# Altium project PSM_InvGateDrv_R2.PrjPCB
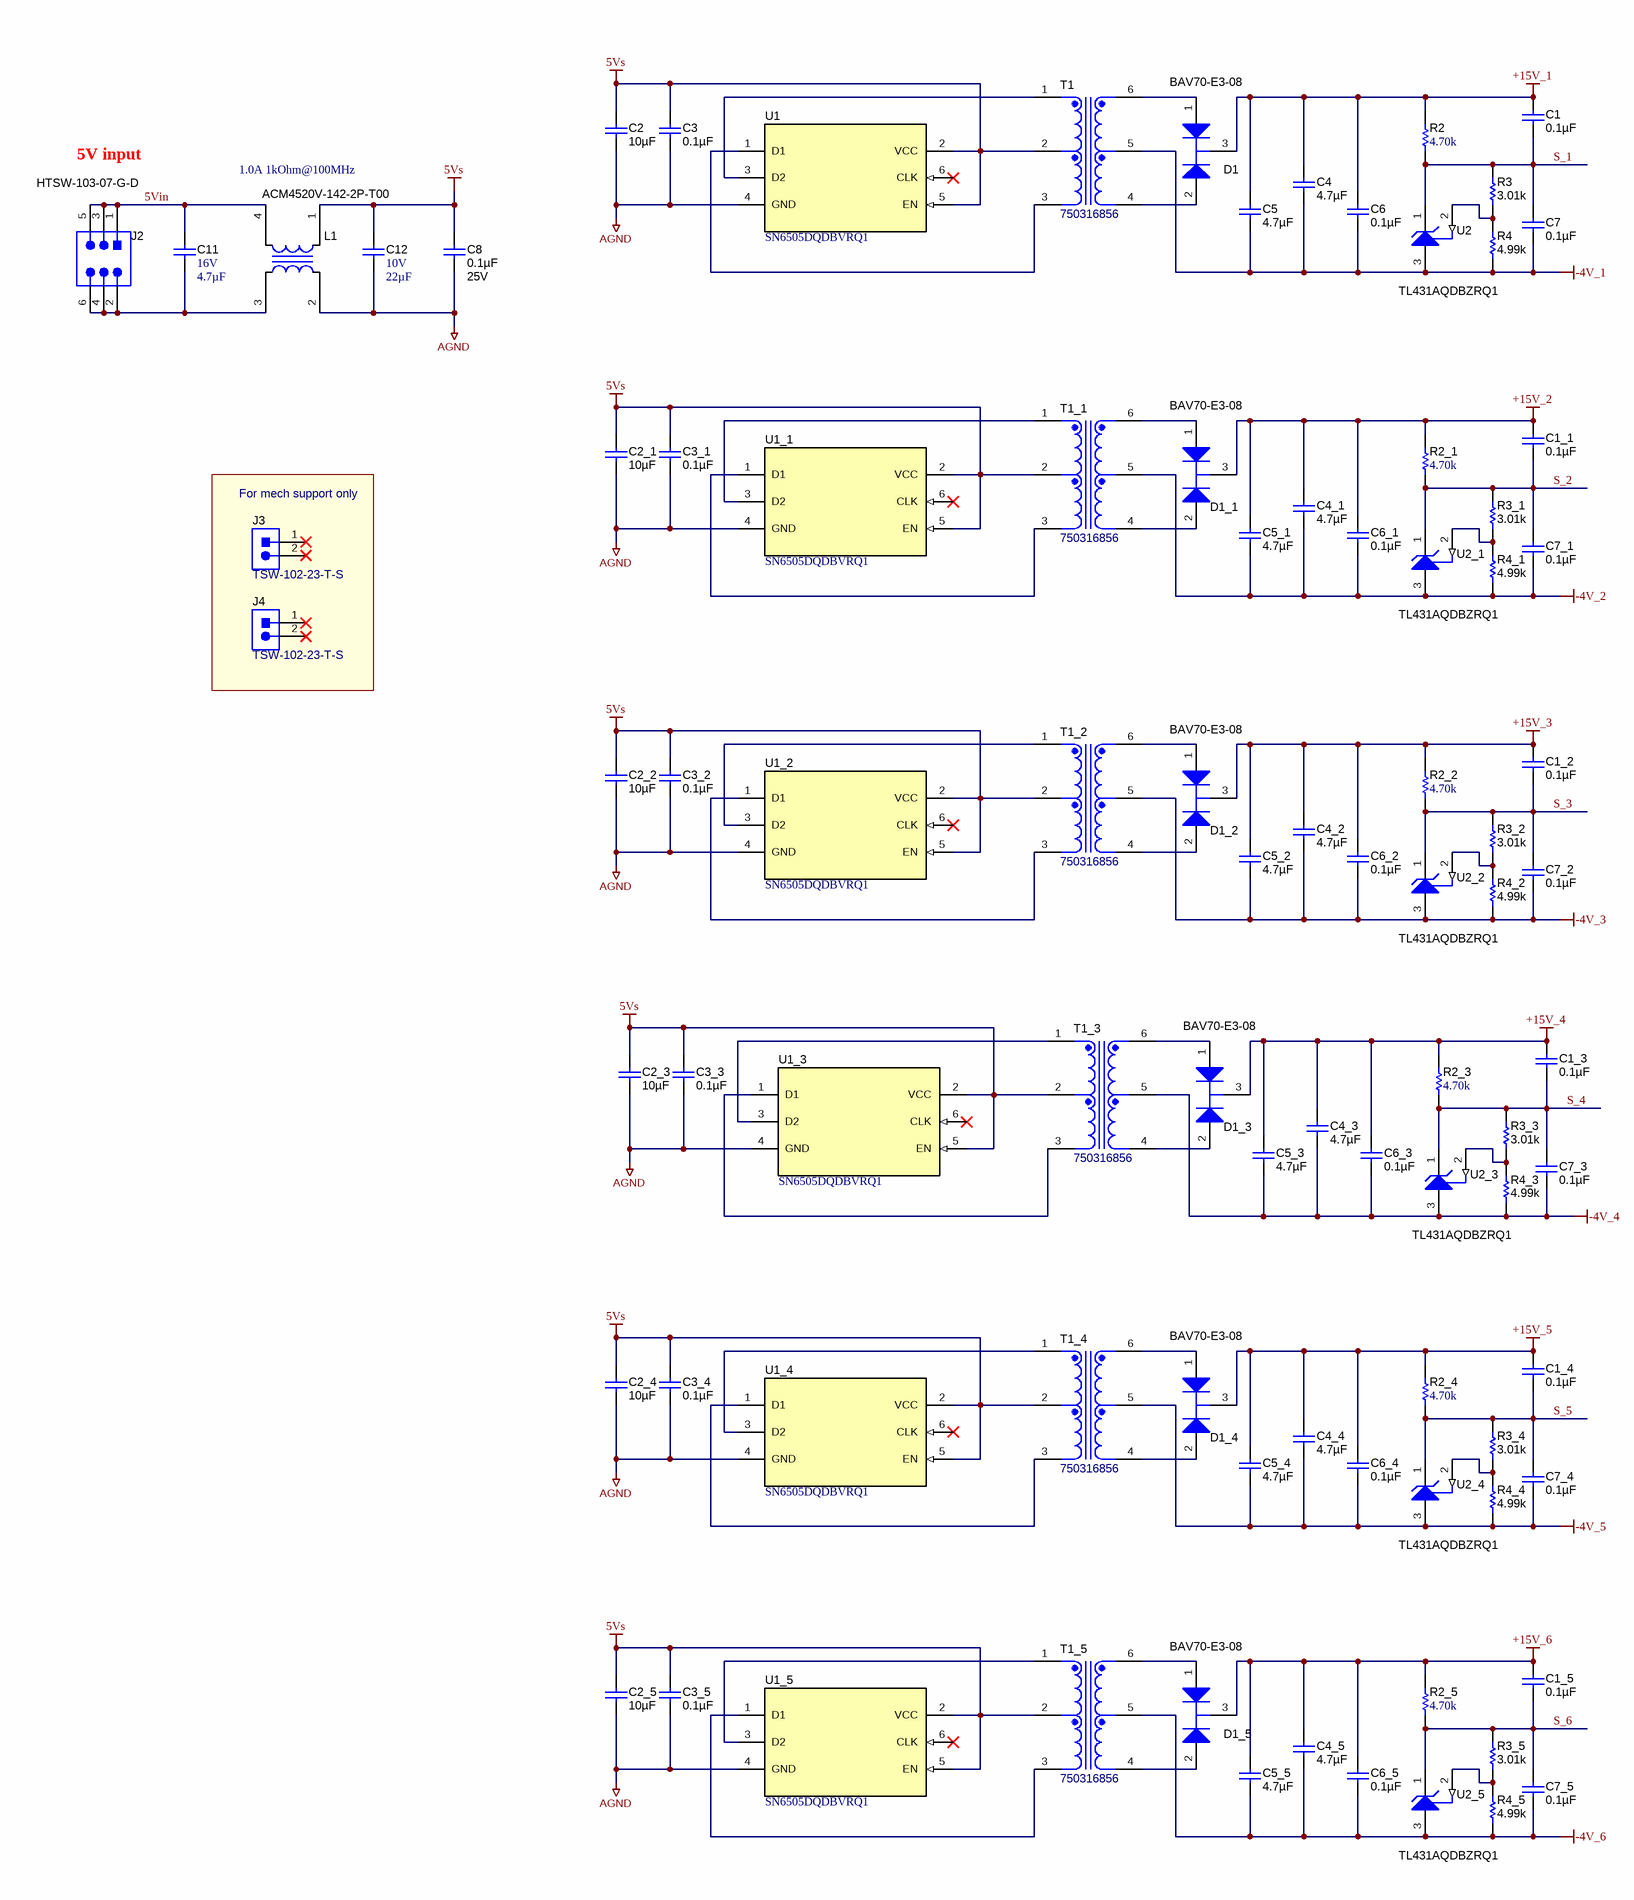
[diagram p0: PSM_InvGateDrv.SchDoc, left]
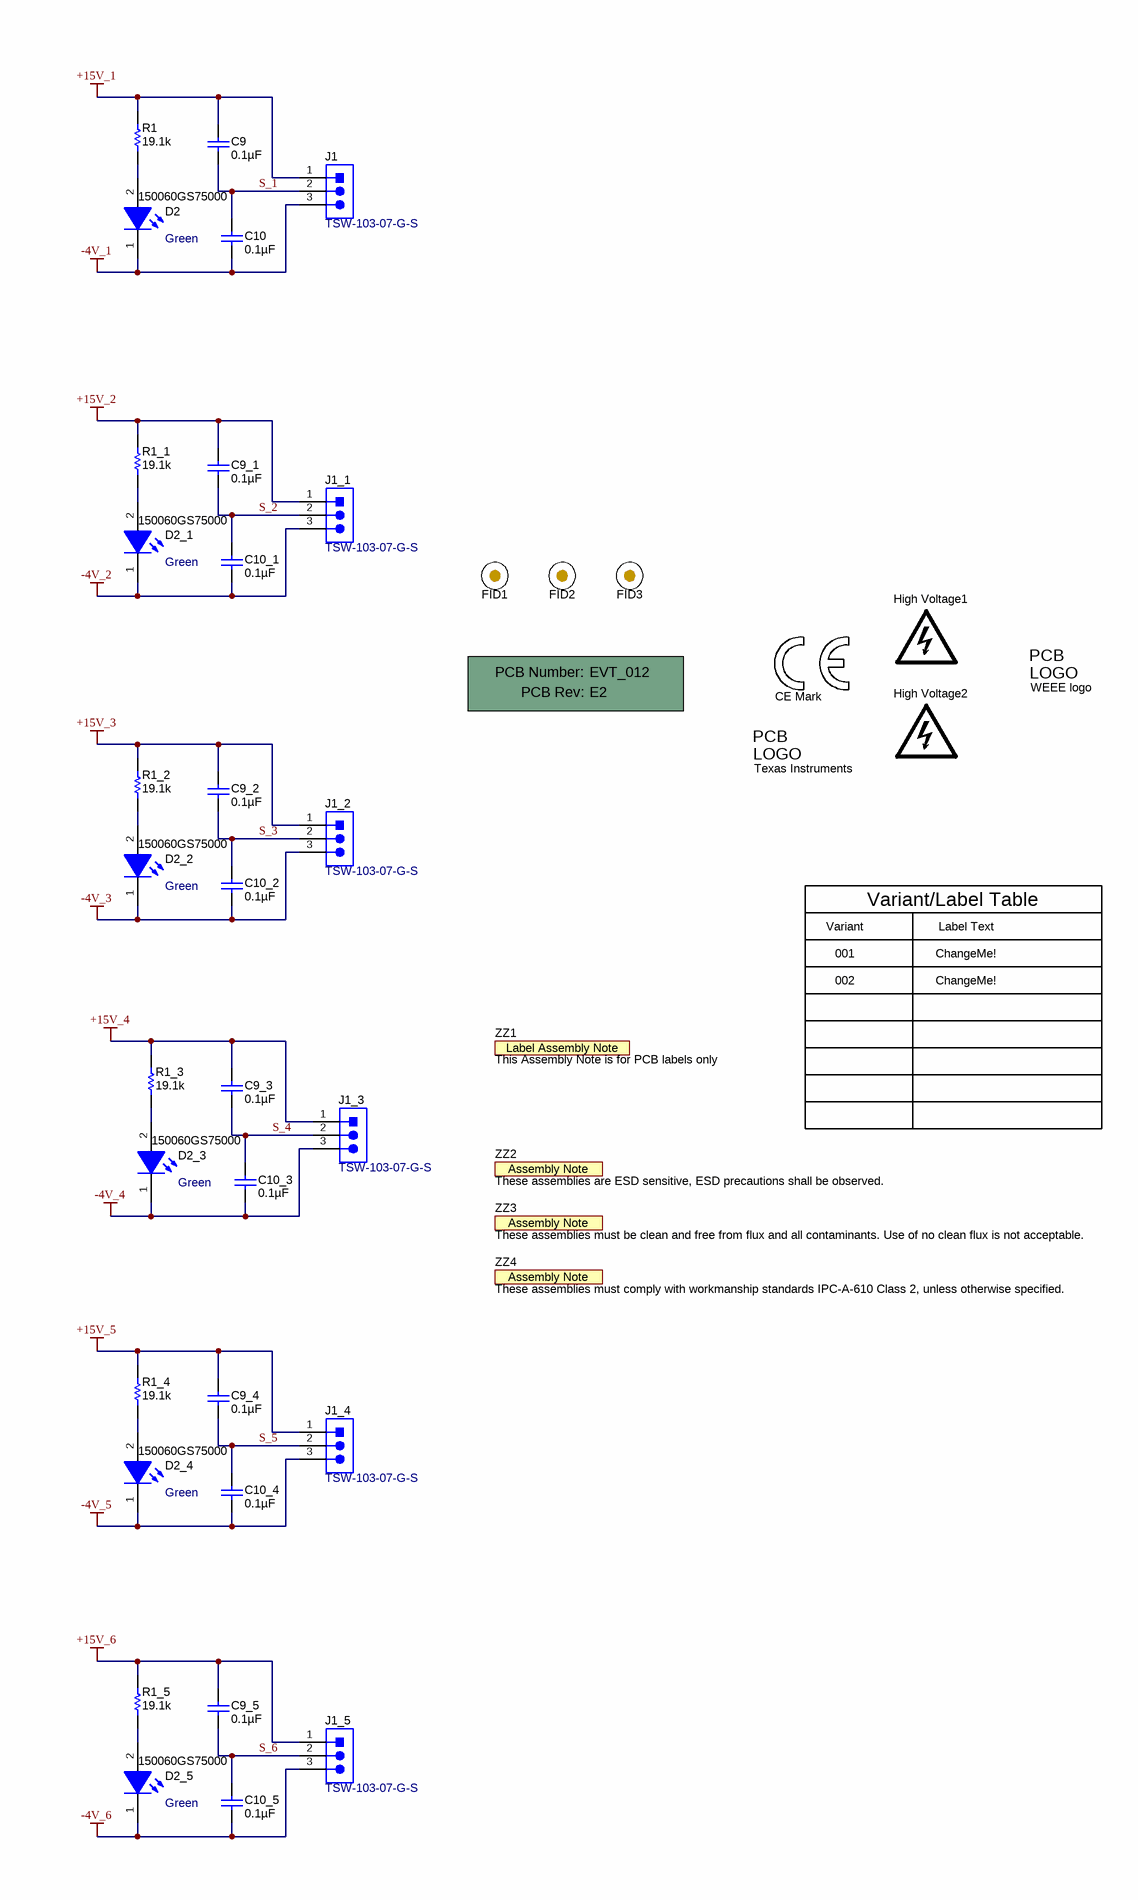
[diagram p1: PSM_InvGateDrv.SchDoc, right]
CopyrightYear: 2019; PCB_Layout: X. Gong / R,Ramesh; PCB_Rev: E2; PRJ_Customer: Public Release; PRJ_Engineer: X.Gong; PRJ_Number: EVT_012; PRJ_Title: Power supply for Traction Gate Driver; SCH_Rev: E2; TechSupport: http://www.ti.com/support; TID: N/A
1 sheet, 134 parts. Net scope: global (net labels, ports and power ports of the same name join across sheets).
Board file: PSM_InvGateDrv_r2.PcbDoc

## Sheet PSM_InvGateDrv.SchDoc
size A2; Date: Not shown in title block; ApprovedBy: Not shown in title block; CheckedBy: Not shown in title block; Author: Not shown in title block; CompanyName: Not shown in title block; Engineer: Not shown in title block; Organization: Not shown in title block; Address1: Not shown in title block; Address2: Not shown in title block; Address3: Not shown in title block; Address4: Not shown in title block; DocumentNumber: 1; Revision: Use project parameter SCH_Rev; SheetNumber: 2; SheetTotal: 3; PageSetup: Record=PageOptions¦CenterHorizontal=True¦CenterVertical=True¦PrintScale=1.00¦XCorrection=1.00¦YCorrection=1.00¦PrintKind=0¦BorderSize=5000000¦LeftOffset=0¦BottomOffset=0¦Orientation=2¦PaperLength=1000¦PaperWidth=1000¦Scale=100¦PaperSource=15¦PrintQuality=600¦MediaType=1¦DitherType=10¦PaperKind=Letter¦PrintScaleMode=1

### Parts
!PCB1  Printed Circuit Board  (value not drawn)  (mechanical)
C1  ValueDisplayed: 0.1µF  [0603]  (hidden comment: CGA3E2X7R1E104K080AA)
C1_1  ValueDisplayed: 0.1µF  [0603]  (hidden comment: CGA3E2X7R1E104K080AA)
C1_2  ValueDisplayed: 0.1µF  [0603]  (hidden comment: CGA3E2X7R1E104K080AA)
C1_3  ValueDisplayed: 0.1µF  [0603]  (hidden comment: CGA3E2X7R1E104K080AA)
C1_4  ValueDisplayed: 0.1µF  [0603]  (hidden comment: CGA3E2X7R1E104K080AA)
C1_5  ValueDisplayed: 0.1µF  [0603]  (hidden comment: CGA3E2X7R1E104K080AA)
C2  ValueDisplayed: 10µF  [0603]  (hidden comment: GRT188C81A106ME13D)
C2_1  ValueDisplayed: 10µF  [0603]  (hidden comment: GRT188C81A106ME13D)
C2_2  ValueDisplayed: 10µF  [0603]  (hidden comment: GRT188C81A106ME13D)
C2_3  ValueDisplayed: 10µF  [0603]  (hidden comment: GRT188C81A106ME13D)
C2_4  ValueDisplayed: 10µF  [0603]  (hidden comment: GRT188C81A106ME13D)
C2_5  ValueDisplayed: 10µF  [0603]  (hidden comment: GRT188C81A106ME13D)
C3  ValueDisplayed: 0.1µF  [0603]  (hidden comment: CGA3E2X7R1E104K080AA)
C3_1  ValueDisplayed: 0.1µF  [0603]  (hidden comment: CGA3E2X7R1E104K080AA)
C3_2  ValueDisplayed: 0.1µF  [0603]  (hidden comment: CGA3E2X7R1E104K080AA)
C3_3  ValueDisplayed: 0.1µF  [0603]  (hidden comment: CGA3E2X7R1E104K080AA)
C3_4  ValueDisplayed: 0.1µF  [0603]  (hidden comment: CGA3E2X7R1E104K080AA)
C3_5  ValueDisplayed: 0.1µF  [0603]  (hidden comment: CGA3E2X7R1E104K080AA)
C4  ValueDisplayed: 4.7µF  [0805_HV]  (hidden comment: GRT21BR61H475KE13L)
C4_1  ValueDisplayed: 4.7µF  [0805_HV]  (hidden comment: GRT21BR61H475KE13L)
C4_2  ValueDisplayed: 4.7µF  [0805_HV]  (hidden comment: GRT21BR61H475KE13L)
C4_3  ValueDisplayed: 4.7µF  [0805_HV]  (hidden comment: GRT21BR61H475KE13L)
C4_4  ValueDisplayed: 4.7µF  [0805_HV]  (hidden comment: GRT21BR61H475KE13L)
C4_5  ValueDisplayed: 4.7µF  [0805_HV]  (hidden comment: GRT21BR61H475KE13L)
C5  ValueDisplayed: 4.7µF  [0805_HV]  (hidden comment: GRT21BR61H475KE13L)
C5_1  ValueDisplayed: 4.7µF  [0805_HV]  (hidden comment: GRT21BR61H475KE13L)
C5_2  ValueDisplayed: 4.7µF  [0805_HV]  (hidden comment: GRT21BR61H475KE13L)
C5_3  ValueDisplayed: 4.7µF  [0805_HV]  (hidden comment: GRT21BR61H475KE13L)
C5_4  ValueDisplayed: 4.7µF  [0805_HV]  (hidden comment: GRT21BR61H475KE13L)
C5_5  ValueDisplayed: 4.7µF  [0805_HV]  (hidden comment: GRT21BR61H475KE13L)
C6  ValueDisplayed: 0.1µF  [0603]  (hidden comment: CGA3E2X7R1E104K080AA)
C6_1  ValueDisplayed: 0.1µF  [0603]  (hidden comment: CGA3E2X7R1E104K080AA)
C6_2  ValueDisplayed: 0.1µF  [0603]  (hidden comment: CGA3E2X7R1E104K080AA)
C6_3  ValueDisplayed: 0.1µF  [0603]  (hidden comment: CGA3E2X7R1E104K080AA)
C6_4  ValueDisplayed: 0.1µF  [0603]  (hidden comment: CGA3E2X7R1E104K080AA)
C6_5  ValueDisplayed: 0.1µF  [0603]  (hidden comment: CGA3E2X7R1E104K080AA)
C7  ValueDisplayed: 0.1µF  [0603]  (hidden comment: CGA3E2X7R1E104K080AA)
C7_1  ValueDisplayed: 0.1µF  [0603]  (hidden comment: CGA3E2X7R1E104K080AA)
C7_2  ValueDisplayed: 0.1µF  [0603]  (hidden comment: CGA3E2X7R1E104K080AA)
C7_3  ValueDisplayed: 0.1µF  [0603]  (hidden comment: CGA3E2X7R1E104K080AA)
C7_4  ValueDisplayed: 0.1µF  [0603]  (hidden comment: CGA3E2X7R1E104K080AA)
C7_5  ValueDisplayed: 0.1µF  [0603]  (hidden comment: CGA3E2X7R1E104K080AA)
C8  ValueDisplayed: 0.1µF  Value2: 25V  [0603]  (hidden comment: CGA3E2X7R1E104K080AA)
C9  ValueDisplayed: 0.1µF  [0603]  (hidden comment: CGA3E2X7R1E104K080AA)
C9_1  ValueDisplayed: 0.1µF  [0603]  (hidden comment: CGA3E2X7R1E104K080AA)
C9_2  ValueDisplayed: 0.1µF  [0603]  (hidden comment: CGA3E2X7R1E104K080AA)
C9_3  ValueDisplayed: 0.1µF  [0603]  (hidden comment: CGA3E2X7R1E104K080AA)
C9_4  ValueDisplayed: 0.1µF  [0603]  (hidden comment: CGA3E2X7R1E104K080AA)
C9_5  ValueDisplayed: 0.1µF  [0603]  (hidden comment: CGA3E2X7R1E104K080AA)
C10  ValueDisplayed: 0.1µF  [0603]  (hidden comment: CGA3E2X7R1E104K080AA)
C10_1  ValueDisplayed: 0.1µF  [0603]  (hidden comment: CGA3E2X7R1E104K080AA)
C10_2  ValueDisplayed: 0.1µF  [0603]  (hidden comment: CGA3E2X7R1E104K080AA)
C10_3  ValueDisplayed: 0.1µF  [0603]  (hidden comment: CGA3E2X7R1E104K080AA)
C10_4  ValueDisplayed: 0.1µF  [0603]  (hidden comment: CGA3E2X7R1E104K080AA)
C10_5  ValueDisplayed: 0.1µF  [0603]  (hidden comment: CGA3E2X7R1E104K080AA)
C11  VDC_V: 16V  ValueDisplayed: 4.7µF  [0603]  (hidden comment: GRT188R61C475KE13D)
C12  VDC_V: 10V  ValueDisplayed: 22µF  [1206_190]  (hidden comment: GRJ31CR71A226KE12L)
D1  BAV70-E3-08  [SOT-23]
D1_1  BAV70-E3-08  [SOT-23]
D1_2  BAV70-E3-08  [SOT-23]
D1_3  BAV70-E3-08  [SOT-23]
D1_4  BAV70-E3-08  [SOT-23]
D1_5  BAV70-E3-08  [SOT-23]
D2  150060GS75000  value Green  [WL-SMCW_GREEN]
D2_1  150060GS75000  value Green  [WL-SMCW_GREEN]
D2_2  150060GS75000  value Green  [WL-SMCW_GREEN]
D2_3  150060GS75000  value Green  [WL-SMCW_GREEN]
D2_4  150060GS75000  value Green  [WL-SMCW_GREEN]
D2_5  150060GS75000  value Green  [WL-SMCW_GREEN]
FID1  Fiducial  [Fiducial10-20]  (value not drawn)
FID2  Fiducial  [Fiducial10-20]  (value not drawn)
FID3  Fiducial  [Fiducial10-20]  (value not drawn)
High_Voltage1  DANGER HIGH VOLTAGE  [IEC_HighVoltage_Small]  (value not drawn)  (no BOM)
High_Voltage2  DANGER HIGH VOLTAGE  [IEC_HighVoltage_Small]  (value not drawn)  (no BOM)
J1  TSW-103-07-G-S  [TSW-103-07-G-S]
J1_1  TSW-103-07-G-S  [TSW-103-07-G-S]
J1_2  TSW-103-07-G-S  [TSW-103-07-G-S]
J1_3  TSW-103-07-G-S  [TSW-103-07-G-S]
J1_4  TSW-103-07-G-S  [TSW-103-07-G-S]
J1_5  TSW-103-07-G-S  [TSW-103-07-G-S]
J2  HTSW-103-07-G-D  [Samtec_HTSW-103-07-x-D]
J3  TSW-102-23-T-S  [Samtec_TSW-102-23-X-S]
J4  TSW-102-23-T-S  [Samtec_TSW-102-23-X-S]
L1  ACM4520V-142-2P-T00  [TDK_ACM4520]
Logo1  CE Mark  [CE_Mark_5mm]  (no BOM)
Logo2  WEEE logo  [WEEE_Minimum]  (no BOM)
Logo3  Texas Instruments  [TI_Stacked_Overlay_Small]  (no BOM)
R1  ValueDisplayed: 19.1k  [0805_HV]  (hidden comment: CRCW080519K1FKEA)
R1_1  ValueDisplayed: 19.1k  [0805_HV]  (hidden comment: CRCW080519K1FKEA)
R1_2  ValueDisplayed: 19.1k  [0805_HV]  (hidden comment: CRCW080519K1FKEA)
R1_3  ValueDisplayed: 19.1k  [0805_HV]  (hidden comment: CRCW080519K1FKEA)
R1_4  ValueDisplayed: 19.1k  [0805_HV]  (hidden comment: CRCW080519K1FKEA)
R1_5  ValueDisplayed: 19.1k  [0805_HV]  (hidden comment: CRCW080519K1FKEA)
R2  ValueDisplayed: 4.70k  [0805_HV]  (hidden comment: ERJ-P06F4701V)
R2_1  ValueDisplayed: 4.70k  [0805_HV]  (hidden comment: ERJ-P06F4701V)
R2_2  ValueDisplayed: 4.70k  [0805_HV]  (hidden comment: ERJ-P06F4701V)
R2_3  ValueDisplayed: 4.70k  [0805_HV]  (hidden comment: ERJ-P06F4701V)
R2_4  ValueDisplayed: 4.70k  [0805_HV]  (hidden comment: ERJ-P06F4701V)
R2_5  ValueDisplayed: 4.70k  [0805_HV]  (hidden comment: ERJ-P06F4701V)
R3  ValueDisplayed: 3.01k  [0603]  (hidden comment: RT0603DRE073K01L)
R3_1  ValueDisplayed: 3.01k  [0603]  (hidden comment: RT0603DRE073K01L)
R3_2  ValueDisplayed: 3.01k  [0603]  (hidden comment: RT0603DRE073K01L)
R3_3  ValueDisplayed: 3.01k  [0603]  (hidden comment: RT0603DRE073K01L)
R3_4  ValueDisplayed: 3.01k  [0603]  (hidden comment: RT0603DRE073K01L)
R3_5  ValueDisplayed: 3.01k  [0603]  (hidden comment: RT0603DRE073K01L)
R4  ValueDisplayed: 4.99k  [0603]  (hidden comment: RT0603DRE074K99L)
R4_1  ValueDisplayed: 4.99k  [0603]  (hidden comment: RT0603DRE074K99L)
R4_2  ValueDisplayed: 4.99k  [0603]  (hidden comment: RT0603DRE074K99L)
R4_3  ValueDisplayed: 4.99k  [0603]  (hidden comment: RT0603DRE074K99L)
R4_4  ValueDisplayed: 4.99k  [0603]  (hidden comment: RT0603DRE074K99L)
R4_5  ValueDisplayed: 4.99k  [0603]  (hidden comment: RT0603DRE074K99L)
T1  750316856  [Wurth_750316856]
T1_1  750316856  [Wurth_750316856]
T1_2  750316856  [Wurth_750316856]
T1_3  750316856  [Wurth_750316856]
T1_4  750316856  [Wurth_750316856]
T1_5  750316856  [Wurth_750316856]
U1  SN6505DQDBVRQ1  [DBV0006A_N]
U1_1  SN6505DQDBVRQ1  [DBV0006A_N]
U1_2  SN6505DQDBVRQ1  [DBV0006A_N]
U1_3  SN6505DQDBVRQ1  [DBV0006A_N]
U1_4  SN6505DQDBVRQ1  [DBV0006A_N]
U1_5  SN6505DQDBVRQ1  [DBV0006A_N]
U2  TL431AQDBZRQ1  [DBZ0003A_N]
U2_1  TL431AQDBZRQ1  [DBZ0003A_N]
U2_2  TL431AQDBZRQ1  [DBZ0003A_N]
U2_3  TL431AQDBZRQ1  [DBZ0003A_N]
U2_4  TL431AQDBZRQ1  [DBZ0003A_N]
U2_5  TL431AQDBZRQ1  [DBZ0003A_N]
ZZ1  This Assembly Note is for PCB labels only  [AssemblyNoteLabel]  (no BOM)
ZZ2  These assemblies are ESD sensitive, ESD precautions shall be observed.  [AssemblyNote]  (no BOM)
ZZ3  These assemblies must be clean and free from flux and all contaminants. Use of no clean flux is not acceptable.  [AssemblyNote]  (no BOM)
ZZ4  These assemblies must comply with workmanship standards IPC-A-610 Class 2, unless otherwise specified.  [AssemblyNote]  (no BOM)

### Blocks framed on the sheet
For mech support only: J3 J4

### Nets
5Vs: C2.1 C2_1.1 C2_2.1 C2_3.1 C2_4.1 C2_5.1 C3.1 C3_1.1 C3_2.1 C3_3.1 C3_4.1 C3_5.1 C8.1 C12.1 L1.1 T1.2 T1_1.2 T1_2.2 T1_3.2 T1_4.2 T1_5.2 U1.2(VCC) U1.5(EN) U1_1.2(VCC) U1_1.5(EN) U1_2.2(VCC) U1_2.5(EN) U1_3.2(VCC) U1_3.5(EN) U1_4.2(VCC) U1_4.5(EN) U1_5.2(VCC) U1_5.5(EN)
+15V_1: C1.1 C4.1 C5.1 C6.1 C9.1 D1.3(C) J1.1 R1.2 R2.2
+15V_2: C1_1.1 C4_1.1 C5_1.1 C6_1.1 C9_1.1 D1_1.3(C) J1_1.1 R1_1.2 R2_1.2
+15V_3: C1_2.1 C4_2.1 C5_2.1 C6_2.1 C9_2.1 D1_2.3(C) J1_2.1 R1_2.2 R2_2.2
+15V_4: C1_3.1 C4_3.1 C5_3.1 C6_3.1 C9_3.1 D1_3.3(C) J1_3.1 R1_3.2 R2_3.2
+15V_5: C1_4.1 C4_4.1 C5_4.1 C6_4.1 C9_4.1 D1_4.3(C) J1_4.1 R1_4.2 R2_4.2
+15V_6: C1_5.1 C4_5.1 C5_5.1 C6_5.1 C9_5.1 D1_5.3(C) J1_5.1 R1_5.2 R2_5.2
-4V_1: C4.2 C5.2 C6.2 C7.2 C10.2 D2.1(K) J1.3 R4.1 T1.5 U2.3(ANODE)
-4V_2: C4_1.2 C5_1.2 C6_1.2 C7_1.2 C10_1.2 D2_1.1(K) J1_1.3 R4_1.1 T1_1.5 U2_1.3(ANODE)
-4V_3: C4_2.2 C5_2.2 C6_2.2 C7_2.2 C10_2.2 D2_2.1(K) J1_2.3 R4_2.1 T1_2.5 U2_2.3(ANODE)
-4V_4: C4_3.2 C5_3.2 C6_3.2 C7_3.2 C10_3.2 D2_3.1(K) J1_3.3 R4_3.1 T1_3.5 U2_3.3(ANODE)
-4V_5: C4_4.2 C5_4.2 C6_4.2 C7_4.2 C10_4.2 D2_4.1(K) J1_4.3 R4_4.1 T1_4.5 U2_4.3(ANODE)
-4V_6: C4_5.2 C5_5.2 C6_5.2 C7_5.2 C10_5.2 D2_5.1(K) J1_5.3 R4_5.1 T1_5.5 U2_5.3(ANODE)
AGND: C2.2 C2_1.2 C2_2.2 C2_3.2 C2_4.2 C2_5.2 C3.2 C3_1.2 C3_2.2 C3_3.2 C3_4.2 C3_5.2 C8.2 C12.2 L1.2 U1.4(GND) U1_1.4(GND) U1_2.4(GND) U1_3.4(GND) U1_4.4(GND) U1_5.4(GND)
5Vin: C11.1 J2.1 J2.3 J2.5 L1.4
S_1: C1.2 C7.1 C9.2 C10.1 J1.2 R2.1 R3.2 U2.1(CATHODE)
S_2: C1_1.2 C7_1.1 C9_1.2 C10_1.1 J1_1.2 R2_1.1 R3_1.2 U2_1.1(CATHODE)
S_3: C1_2.2 C7_2.1 C9_2.2 C10_2.1 J1_2.2 R2_2.1 R3_2.2 U2_2.1(CATHODE)
S_4: C1_3.2 C7_3.1 C9_3.2 C10_3.1 J1_3.2 R2_3.1 R3_3.2 U2_3.1(CATHODE)
S_5: C1_4.2 C7_4.1 C9_4.2 C10_4.1 J1_4.2 R2_4.1 R3_4.2 U2_4.1(CATHODE)
S_6: C1_5.2 C7_5.1 C9_5.2 C10_5.1 J1_5.2 R2_5.1 R3_5.2 U2_5.1(CATHODE)
NetC11_2: C11.2 J2.2 J2.4 J2.6 L1.3
NetD1_1: D1.1(A) T1.6
NetD1_1_1: D1_1.1(A) T1_1.6
NetD1_1_2: D1_1.2(K) T1_1.4
NetD1_2: D1.2(K) T1.4
NetD1_2_1: D1_2.1(A) T1_2.6
NetD1_2_2: D1_2.2(K) T1_2.4
NetD1_3_1: D1_3.1(A) T1_3.6
NetD1_3_2: D1_3.2(K) T1_3.4
NetD1_4_1: D1_4.1(A) T1_4.6
NetD1_4_2: D1_4.2(K) T1_4.4
NetD1_5_1: D1_5.1(A) T1_5.6
NetD1_5_2: D1_5.2(K) T1_5.4
NetD2_1_2: D2_1.2(A) R1_1.1
NetD2_2: D2.2(A) R1.1
NetD2_2_2: D2_2.2(A) R1_2.1
NetD2_3_2: D2_3.2(A) R1_3.1
NetD2_4_2: D2_4.2(A) R1_4.1
NetD2_5_2: D2_5.2(A) R1_5.1
NetR3_1: R3.1 R4.2 U2.2(REF)
NetR3_1_1: R3_1.1 R4_1.2 U2_1.2(REF)
NetR3_2_1: R3_2.1 R4_2.2 U2_2.2(REF)
NetR3_3_1: R3_3.1 R4_3.2 U2_3.2(REF)
NetR3_4_1: R3_4.1 R4_4.2 U2_4.2(REF)
NetR3_5_1: R3_5.1 R4_5.2 U2_5.2(REF)
NetT1_1: T1.1 U1.3(D2)
NetT1_1_1: T1_1.1 U1_1.3(D2)
NetT1_1_3: T1_1.3 U1_1.1(D1)
NetT1_2_1: T1_2.1 U1_2.3(D2)
NetT1_2_3: T1_2.3 U1_2.1(D1)
NetT1_3: T1.3 U1.1(D1)
NetT1_3_1: T1_3.1 U1_3.3(D2)
NetT1_3_3: T1_3.3 U1_3.1(D1)
NetT1_4_1: T1_4.1 U1_4.3(D2)
NetT1_4_3: T1_4.3 U1_4.1(D1)
NetT1_5_1: T1_5.1 U1_5.3(D2)
NetT1_5_3: T1_5.3 U1_5.1(D1)

Not connected (* = marked no-connect by the designer): J3 1* 2*; J4 1* 2*; U1 6(CLK)*; U1_1 6(CLK)*; U1_2 6(CLK)*; U1_3 6(CLK)*; U1_4 6(CLK)*; U1_5 6(CLK)*

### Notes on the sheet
- 5V input
- 1.0A 1kOhm@100MHz
- Variant
- Variant/Label Table
- Label Text
- 001
- 002
- ChangeMe!

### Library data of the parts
!PCB1 = CMP-0003618-2: Manufacturer: Any; PartNumber: EVT_012
C1 C1_1-C1_5 C3 C3_1-C3_5 C6 C6_1-C6_5 C7 C7_1-C7_5 C9 C9_1-C9_5 C10 C10_1-C10_5 = CGA3E2X7R1E104K080AA: CAP, CERM, 0.1 µF, 25 V,+/- 10%, X7R, AEC-Q200 Grade 1, 0603; Manufacturer: TDK; Polarized: N; CompType: Capacitor; Value: 0.1uF; U/M: EA; Cap_F: 0.0000001; Tolerance_%: 10; VDC_V: 25; Value2: 25V; TaMin_C: -55; TaMax_C: 125; SizeArea_mm2: 1.28; SizeAreaWB_mm2: 4.68; SizeX_mm: 1.6; SizeY_mm: 0.8; SizeZ_mm: 1; AEC Category: Q200; AEC Qualified: Y
C2 C2_1-C2_5 = GRT188C81A106ME13D: CAP, CERM, 10 µF, 10 V,+/- 20%, X6S, AEC-Q200 Grade 2, 0603; Manufacturer: MuRata; Polarized: N; CompType: Capacitor; Value: 10uF; U/M: EA; Cap_F: 0.00001; Tolerance_%: 20; VDC_V: 10; Value2: 10V; TaMin_C: -55; TaMax_C: 105; SizeArea_mm2: 1.28; SizeAreaWB_mm2: 4.68; SizeX_mm: 1.6; SizeY_mm: 0.8; SizeZ_mm: 1; AEC Category: Q200; AEC Qualified: Y; AEC Grade: 2; Green_Lifecycle: Active; Green_REACh: Passed
C4 C4_1-C4_5 C5 C5_1-C5_5 = GRT21BR61H475KE13L: CAP, CERM, 4.7 µF, 50 V,+/- 10%, X5R, AEC-Q200 Grade 3, 0805; Manufacturer: MuRata; Polarized: N; CompType: Capacitor; Value: 4.7uF; U/M: EA; Cap_F: 0.0000047; Tolerance_%: 10; VDC_V: 50; Value2: 50V; TaMin_C: -55; TaMax_C: 85; Cap_Case: 0805; SizeArea_mm2: 2.5; SizeAreaWB_mm2: 6.75; SizeX_mm: 2; SizeY_mm: 1.25; SizeZ_mm: 1.45; AEC Category: Q200; AEC Qualified: Y; AEC Grade: 3
C8 = CGA3E2X7R1E104K080AA: CAP, CERM, 0.1 µF, 25 V,+/- 10%, X7R, AEC-Q200 Grade 1, 0603; Manufacturer: TDK; Polarized: N; CompType: Capacitor; Value: 0.1uF; U/M: EA; Cap_F: 0.0000001; Tolerance_%: 10; VDC_V: 25; TaMin_C: -55; TaMax_C: 125; SizeArea_mm2: 1.28; SizeAreaWB_mm2: 4.68; SizeX_mm: 1.6; SizeY_mm: 0.8; SizeZ_mm: 1; AEC Category: Q200; AEC Qualified: Y
C11 = CMP-0081052-1: CAP, CERM, 4.7 µF, 16 V,+/- 10%, X5R, AEC-Q200 Grade 3, 0603; Manufacturer: MuRata; SizeAreaWB_mm2: 4.68; SizeArea_mm2: 1.28; AEC Qualified: Y; AEC Category: Q200; Value: 4.7uF; TaMax_C: 85°C; SizeZ_mm: 1; AEC Grade: 3; Polarized: N; TaMin_C: -55°C; SizeY_mm: 0.8; U/M: EA; SizeX_mm: 1.6
C12 = CMP-0074691-1: CAP, CERM, 22 µF, 10 V,+/- 10%, X7R, 1206; Manufacturer: MuRata; TaMin_C: -55°C; Polarized: N; SizeAreaWB_mm2: 10.92; U/M: EA; Value: 22uF; TaMax_C: 125°C; SizeZ_mm: 1.9; SizeX_mm: 3.2; SizeY_mm: 1.6; Cap_Case: 1206; SizeArea_mm2: 5.12; AEC Category: Q200
D1 D1_1-D1_5 = BAV70-E3-08: Diode, Switching, 70 V, 0.25 A, AEC-Q101, SOT-23; Manufacturer: Vishay-Semiconductor; SymbolCreator: a0412235; U/M: EA; Vf_V: 1.25; Value: 70V; Value1: 0.25A; Value2: 1.25V; Io_A: 0.25; Vr_V: 70; TJmax_C: 150; SizeAreaWB_mm2: 14; SizeArea_mm2: 7.5; SizeX_mm: 2.5; SizeY_mm: 3; SizeZ_mm: 1.1; AEC Category: Q101; AEC Qualified: Y; Green_Lifecycle: Not Set; Green_REACh: Incomplete
D2 D2_1-D2_5 = CMP-0002905-2: LED, Green, SMD; Manufacturer: Wurth Elektronik; Type: InGaN; Vf_V: 3.2V; Io_A: 20mA; Tjmax_C: 85°C; Value1: W; Angle: 140
FID1-FID3 = CMP-0077181-1: Fiducial mark.  There is nothing to buy or mount.
High_Voltage1 High_Voltage2 = CMP-0074835-1: IEC 61010-1 High Voltage Warning; SymbolCreator: a0412235
J1 J1_1-J1_5 = CMP-0075407-2: Header, 100mil, 3x1, Gold, TH; Manufacturer: Samtec; Pitch_mm: 2.54; Cert_VDE: N; Gender: Male; Cert_CSA: Y; Voltage_V: 550V; Green_REACh: Passed; Current_A: 6.3A; Green_Lifecycle: Active; Row_Count: 1
J2 = CMP-0055587-2: Header, 2.54mm, 3x2, Gold, TH; Manufacturer: Samtec; Green_Lifecycle: Active; Shrouded: N; Gender: Male; Cert_CSA: Y; Green_REACh: Passed; Row_Count: 2; RowSpacing_mm: 2.54
J3 J4 = CMP-0084558-1: Header, 2.54mm, 2x1, Tin, TH; Manufacturer: Samtec; Cert_UL: Y; Row_Count: 1; Pitch_mm: 2.54; Gender: Male; Current_A: 6.3A; Voltage_V: 550V; Shrouded: N
L1 = CMP-0084502-1: Coupled inductor,  ohm, AEC-Q200 Grade 1, SMD; Manufacturer: TDK; AEC Grade: 1; AEC Category: Q200; AEC Qualified: Y
Logo1 = CMP-0074844-1: SymbolCreator: a0412235
Logo2 = CMP-0074769-1
Logo3 = CMP-0074838-1: Texas Instrument Corporate Signature; SymbolCreator: a0412235; Lib Reference: TI_Logo; Library Reference: Logo
R1 R1_1-R1_5 = CRCW080519K1FKEA: RES, 19.1 k, 1%, 0.125 W, 0805; Manufacturer: Vishay-Dale; CompType: Resistor; Value: 19.1k; Res_ohm: 19100; Value_Code: 19k1; Tolerance_%: 1; Power_W: 0.125; Value2: 0.125W; VDC_V: 150; TempCo: 100 ppm/C; SizeArea_mm2: 2.5; SizeX_mm: 2; SizeY_mm: 1.25; SizeZ_mm: 1.45; EIA_Code: E96; U/M: EA; AEC Category: Q200; Green_Lifecycle: Active; Green_REACh: Passed
R2 R2_1-R2_5 = CMP-0021852-2: RES, 4.70 k, 1%, 0.5 W, AEC-Q200 Grade 0, 0805; Manufacturer: Panasonic; Power_W: 500mW; TempCo: 100 ppm/C; Value_Code: 4k70; U/M: EA; Value: 4.70k; Res_ohm: 4.7k; SizeX_mm: 2; SizeY_mm: 1.25; SizeZ_mm: 1.45; Value2: 0.5W; SizeArea_mm2: 2.5; AEC Qualified: Y; VDC_V: 400V; AEC Grade: 0; AEC Category: Q200
R3 R3_1-R3_5 = RT0603DRE073K01L: RES, 3.01 k, 0.5%, 0.1 W, 0603; Manufacturer: Yageo America; CompType: Resistor; Value: 3.01k; Res_ohm: 3010; Value_Code: 3k01; Tolerance_%: 0.5; Power_W: 0.1; Value2: 0.1W; VDC_V: 75; TempCo: 50 ppm/C; SizeArea_mm2: 1.28; SizeX_mm: 1.6; SizeY_mm: 0.8; SizeZ_mm: 1; EIA_Code: E192; U/M: EA; AEC Category: Q200
R4 R4_1-R4_5 = RT0603DRE074K99L: RES, 4.99 k, 0.5%, 0.1 W, 0603; Manufacturer: Yageo America; CompType: Resistor; Value: 4.99k; Res_ohm: 4990; Value_Code: 4k99; Tolerance_%: 0.5; Power_W: 0.1; Value2: 0.1W; VDC_V: 75; TempCo: 50 ppm/C; SizeArea_mm2: 1.28; SizeX_mm: 1.6; SizeY_mm: 0.8; SizeZ_mm: 1; EIA_Code: E192; U/M: EA; AEC Category: Q200; Green_Lifecycle: Active; Green_REACh: Passed
T1 T1_1-T1_5 = CMP-0081897-1: Transformer, 200 uH, SMD; Manufacturer: Wurth Elektronik; LeakageInd_H: 200nH; SizeAreaWB_mm2: 172.525; DCR_ohm: 0.28; Value: 200uH; Lp: 200; SizeZ_mm: 4.2; SizeX_mm: 14.75; SizeY_mm: 8.3; Ns1toNp: 4.67; SizeArea_mm2: 122.425; Ind_H: 200µH; AEC Qualified: N; Rsec1_ohm: 2; AEC Category: Q200
U1 U1_1-U1_5 = CMP-0860735-1: SN6505DQDBVRQ1, DBV0006A (SOT-23-6); Alternate PartNumber: SN6505DQDBVTQ1; Alternate Manufacturer: Texas Instruments; CompType: IC; SizeAreaWB_mm2: 14.82; SizeArea_mm2: 8.12; SizeZ_mm: 1.45; SizeY_mm: 2.9; SizeX_mm: 2.8; AEC Category: Q200
U2 U2_1-U2_5 = TL431AQDBZRQ1: Automotive Catalog Adjustable Precision Shunt Regulator, 34 ppm / degC, 100 mA, -40 to 125 degC, 3-pin SOT-23 (DBZ), Green (RoHS & no Sb/Br); Manufacturer: Texas Instruments; Alternate PartNumber: Equivalent; Initial Accuracy @ 25/deg C(%): 1; Iout/Iz(Max)(mA): 100; Min Iz for Regulation(uA): 600; SubFamily: Shunt Voltage Reference; Temp Coeff(Typ)(ppm/ degree C): 34; VO Adj(Max)(V): 36; VO Adj(Min)(V): 2.495
ZZ1 = CMP-0003616-3
ZZ2 = CMP-0077236-1
ZZ3 = CMP-0077237-1
ZZ4 = CMP-0077238-1

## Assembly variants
001: not fitted FID1 FID2 FID3 R? R?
